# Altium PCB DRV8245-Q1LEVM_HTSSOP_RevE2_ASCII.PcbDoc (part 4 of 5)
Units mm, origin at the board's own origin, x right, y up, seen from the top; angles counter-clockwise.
Board outline 81.9 x 103.6 mm, 4 copper layers (Top Layer, Signal Layer 1, Signal Layer 2, Bottom Layer), stack 1.554 mm thick; 187 components, 116 nets, 590 pads, 1182 vias.
Unrouted connection lines stored in the file: 116.
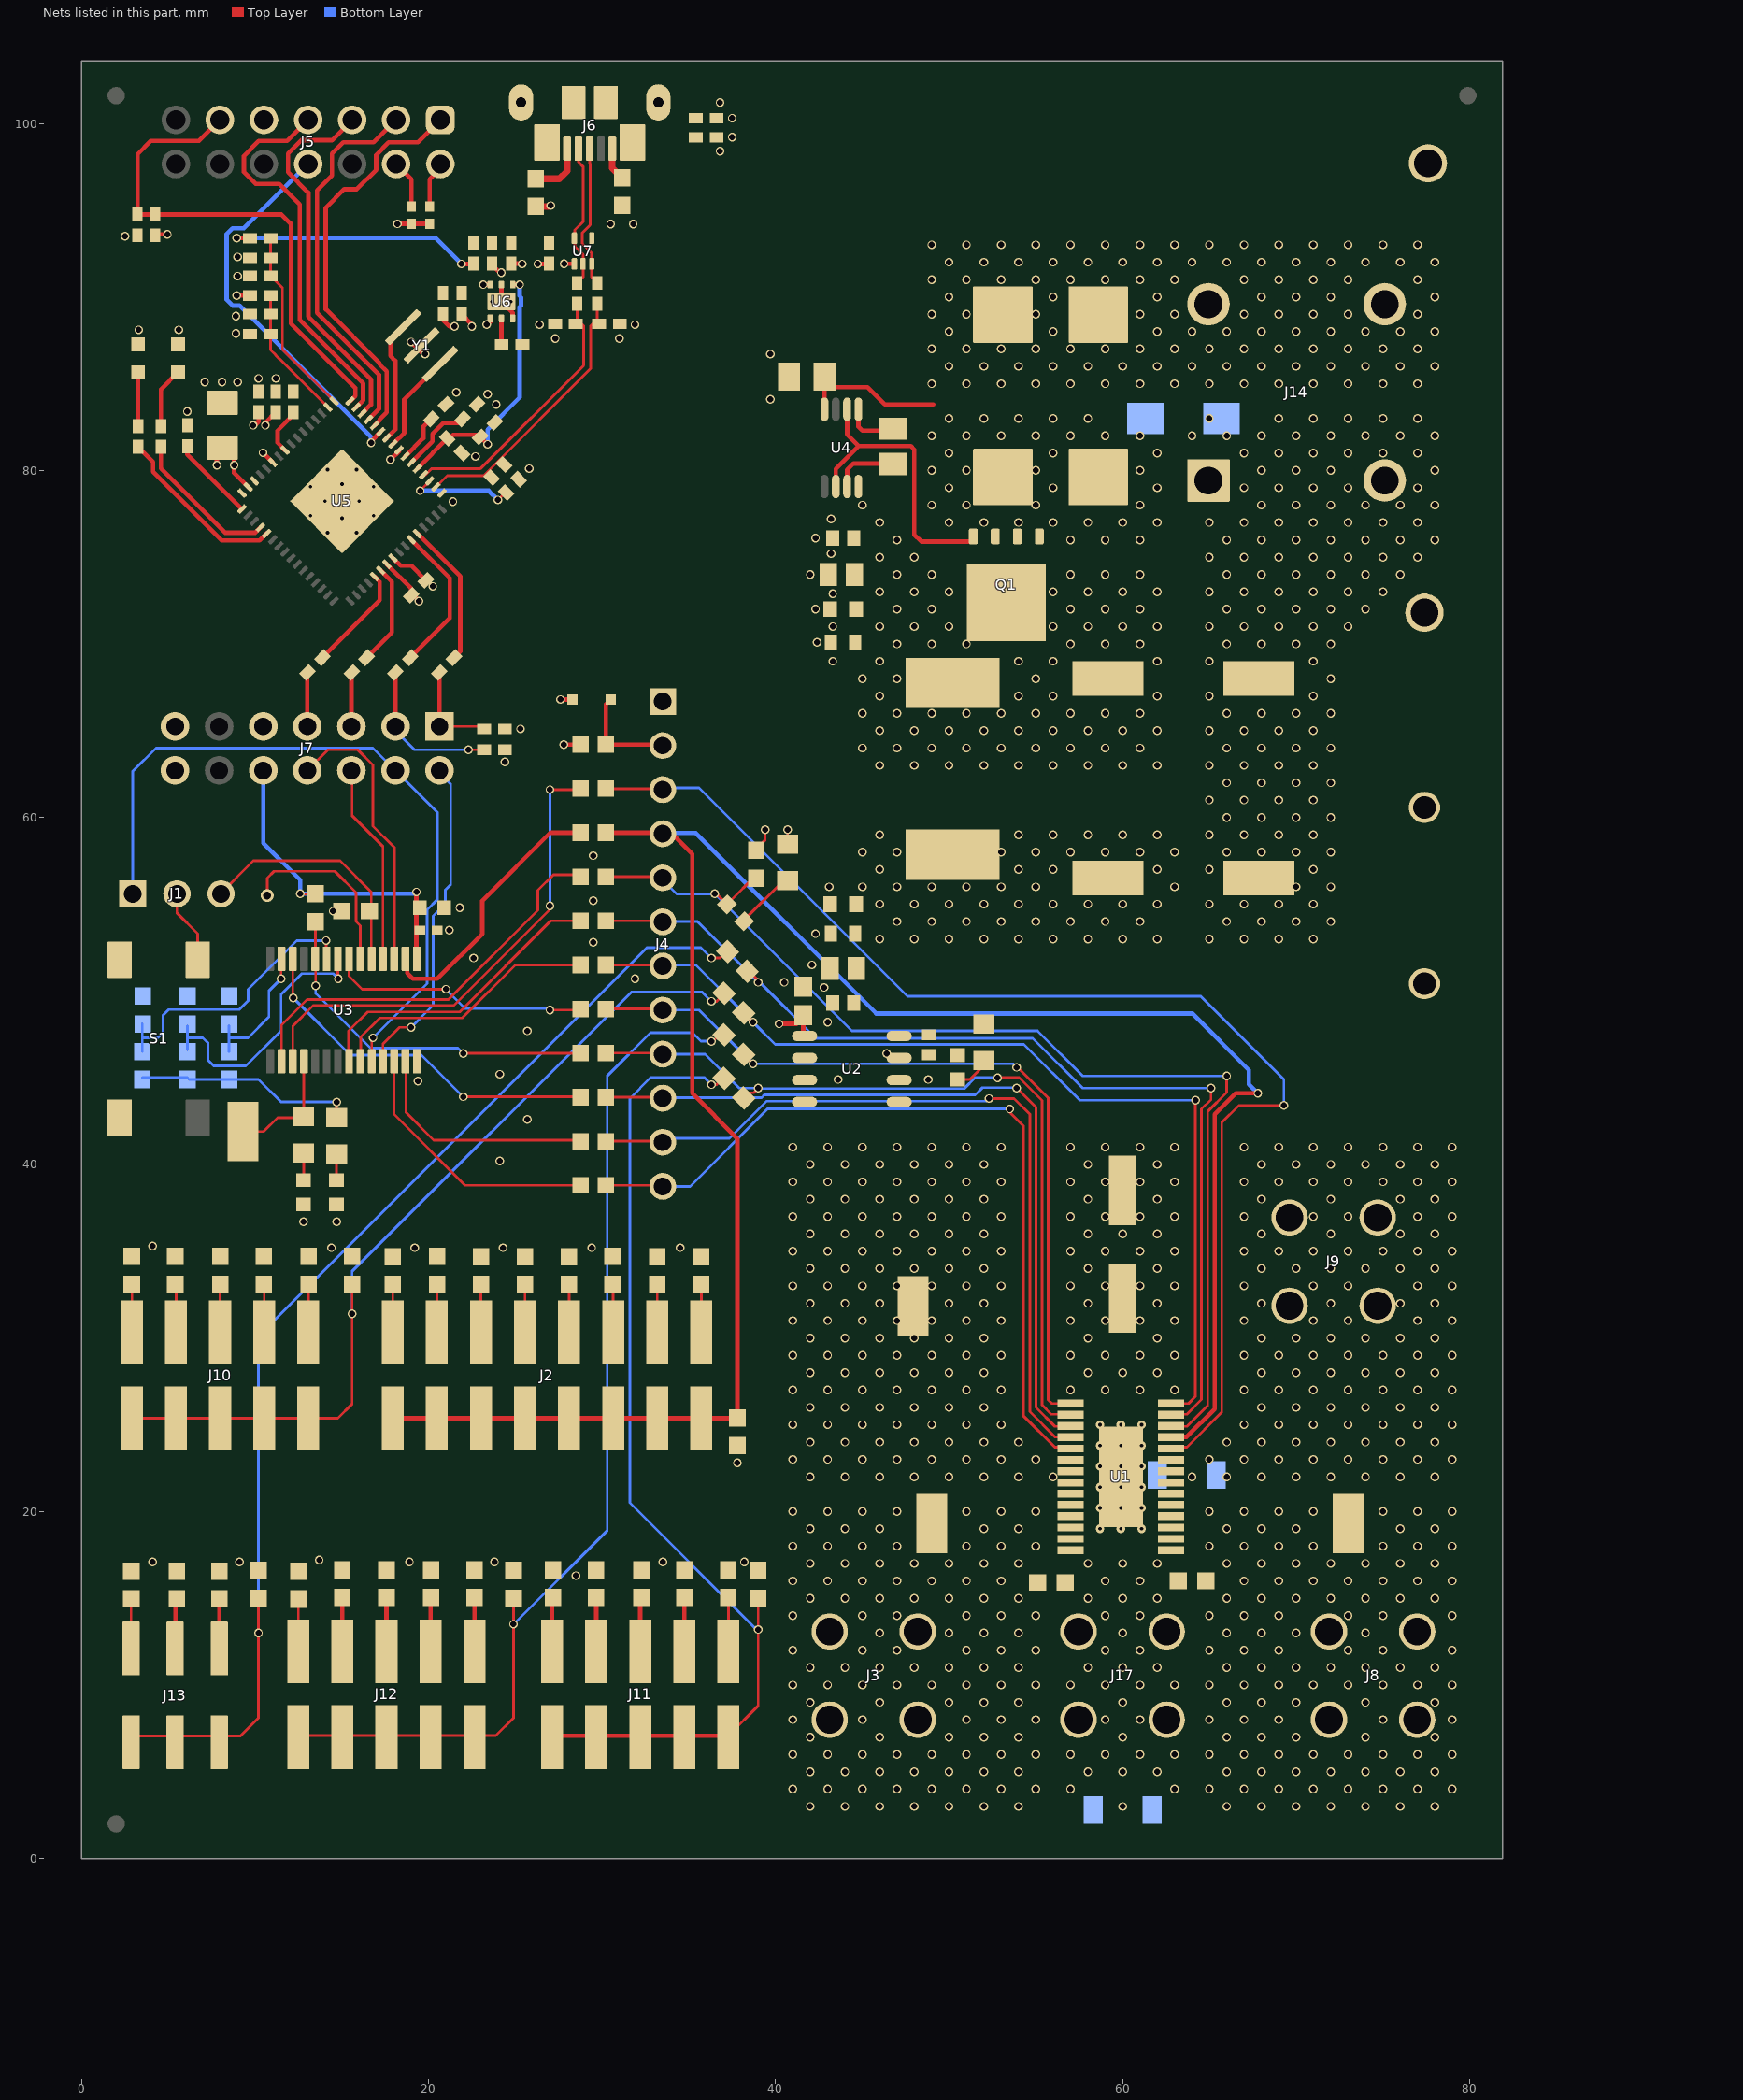
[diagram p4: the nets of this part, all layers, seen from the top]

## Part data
C1: library part CMP-0011164-2, "CAP, AL, 10 uF, 100 V, +/- 20%, AEC-Q200 Grade 3, SMD"
C2 C3: library part CMP-0008709-1, "CAP, CERM, 0.1 uF, 100 V, +/- 10%, X7R, 1206"
C4: library part CMP-13271-000011-1, "CAP CER 0.1UF 50V X7R 0603"
C5: library part CMP-13271-003053-1, "Cap Ceramic 22uF 6.3V X5R ±20% Pad SMD 0603 +85°C T/R"
C6 C13: library part CMP-2007-03579-1, "GRM21BR71H105KA12L"
C7 C12: library part CMP-1035-02591-1, "CAP 100nF 50V ±5% 0603 (1608 Metric) Thickness 1mm SMD"
C8 C11: library part CMP-1035-02321-3, "CAP CER 10000PF 50V X7R 0603"
C9 C10: library part CMP-0011178-2, "CAP, AL, 150 uF, 50 V, +/- 20%, 0.18 ohm, AEC-Q200 Grade 2, SMD"
C14 C15: library part CMP-03020-030804-1, "CAP CER 1000PF 50V X7R 0603"
C16: library part CMP-0007580-1, "CAP, CERM, 100 pF, 50 V, +/- 5%, C0G/NP0, 0805"
C17: library part CMP-0006268-2, "CAP, CERM, 4.7 uF, 10 V, +/- 10%, X5R, 0402"
C18: library part CMP-0064931-4, "CAP, CERM, 0.1 uF, 10 V,+/- 10%, X7R, 0603"
C19: library part CMP-0006269-2, "CAP, CERM, 4.7 uF, 10 V, +/- 20%, X5R, 0402"
C20 C22 C29 C35 C36 C37 C45: library part CMP-0006562-2, "CAP, CERM, 0.1 uF, 10 V, +/- 10%, X5R, 0402"
C21 C24: library part CMP-0006250-2, "CAP, CERM, 33 pF, 50 V, +/- 5%, C0G/NP0, 0402"
C23: library part CMP-0006673-2, "CAP, CERM, 1000 pF, 50 V, +/- 10%, X7R, 0402"
C25 C27 C44: library part CMP-0006570-2, "CAP, CERM, 0.22 uF, 10 V, +/- 10%, X5R, 0402"
C26: library part CMP-0006600-2, "CAP, CERM, 0.47 uF, 16 V, +/- 10%, X5R, 0402"
C28 C33: library part CMP-0064924-2, "CAP, CERM, 1 uF, 10 V,+/- 20%, X5R, 0402"
C30 C32: library part CMP-0006639-2, "CAP, CERM, 0.01 uF, 16 V, +/- 10%, X7R, 0402"
C31: library part CMP-0006594-2, "CAP, CERM, 2.2 uF, 16 V, +/- 10%, X5R, 0402"
C34: library part CMP-0084376-1, "CAP, Tantalum Polymer, 10 µF, 10 V,+/- 20%, 0.08 ohm, 3216-18 SMD"
C38 C39 C40 C41 C42 C43 C46: library part CMP-0007081-4, "CAP, CERM, 1000 pF, 100 V, +/- 10%, X7R, AEC-Q200 Grade 1, 0603"
C47 C48 C49 C50: library part CMP-0064916-2, "CAP, CERM, 10 pF, 50 V,+/- 1%, C0G/NP0, 0402"
C51: library part CMP-0007836-1, "CAP, CERM, 2.2 uF, 50 V, +/- 10%, X5R, 0805"
D1 D3 D7: library part CMP-1426-00009-1, "SMD mono-color Chip LED, WL-SMCW, Bright Green"
D2: library part CMP-1426-00010-1, "SMD mono-color Chip LED, WL-SMCW, Super Red"
D4: library part CMP-08607-000009-1, "TVS DIODE 36V 58.1V DO214AC"
D5: library part CMP-0002947-3, "LED, Red, SMD"
D6: "LED, Green, SMD"
D8: library part CMP-0028882-1, "Diode, Schottky, 40 V, 0.75 A, AEC-Q101, SOD-323"
F1 F2: library part CMP-0077200-3, "Fuse, 30 A, 250 VAC, 100 VDC, SMD"
FID1 FID2 FID3: library part CMP-0077181-1, "Fiducial mark.  There is nothing to buy or mount."
H1 H2 H3 H4: library part CMP-0003620-1, "Bumpon, Hemisphere, 0.44 X 0.20, Clear"
J1: library part CMP-77940-000002-1, "CONN HEADER VERT 3POS 2.54MM"
J2: library part CMP-0075595-1, "Header, 2.54mm, 8x2, Gold, SMT"
J3 J8 J9: library part CMP-0055418-2, "Banana Jack Insul Nylon Red, R/A, TH"
J4: library part CMP-0054586-1, "Header, 2.54 mm, 12x1, Gold, TH"
J5: library part CMP-0086014-1, "Header, 2.54mm, 7x2, Gold, TH"
J6: "Receptacle, USB 2.0, Micro B, 5 Position, R/A, SMT"
J7: library part CMP-0002339-2, "Header, 100mil, 7x2, Tin, TH"
J10 J11 J12: library part CMP-0055598-2, "Header, 2.54mm, 5x2, Gold, SMT"
J13: library part CMP-0079534-2, "Header, 2.54mm, 3x2, Gold, SMT"
J14: library part CMP-0086764-1
J15: library part CMP-0075110-1, "1mm Uninsulated Shorting Plug, 10.16mm spacing, TH"
J17: library part CMP-0055417-1, "Banana Jack Insul Nylon Black, R/A, TH"
L1: library part CMP-0226-00123-1, "SMD High Current Cube Inductor WE-HCC, L=1.00 µH"
L2 L3: library part CMP-0081962-1, "Ferrite Bead, 150 ohm @ 100 MHz, 0.7 A, 0603"
LBL1: library part CMP-0003625-1, "Thermal Transfer Printable Labels, 0.650\" W x 0.200\" H - 10,000 per roll"
Logo1: library part CMP-0074844-1
Logo2: library part CMP-0074838-1, "Texas Instrument Corporate Signature"
Logo3: library part CMP-0074847-1, "FCC_disclaimer"
Logo4: library part CMP-0074769-1
Logo5: library part CMP-0074836-1, "IEC 61010-1 Caution Warning"
LOGO6: library part CMP-0074837-1, "IEC 61010-1 Hot Surface Warning"
Q1: library part CMP-0000714-1, "MOSFET, N-CH, 40 V, 100 A, DQJ0008A (VSONP-8)"
R1 R68: library part CMP-0025886-3, "RES, 10 k, 5%, 0.1 W, 0603"
R2 R3 R20: "RES, 330, 5%, 0.1 W, AEC-Q200 Grade 0, 0603"
R4: library part CMP-0082533-1, "RES, 4.99 k, 1%, 0.1 W, 0603"
R5: library part CMP-0023129-5, "RES, 470, 1%, 0.1 W, 0603"
R6: library part CMP-0023235-5, "RES, 680, 1%, 0.1 W, 0603"
R7: library part CMP-0022895-5, "RES, 1.00 k, 1%, 0.1 W, 0603"
R8: library part CMP-0022883-5, "RES, 1.50 k, 1%, 0.1 W, 0603"
R9: library part CMP-0022986-5, "RES, 2.20 k, 1%, 0.1 W, 0603"
R10: library part CMP-0023081-5, "RES, 3.30 k, 1%, 0.1 W, 0603"
R11: library part CMP-0023153-5, "RES, 4.70 k, 1%, 0.1 W, 0603"
R12: library part CMP-0023253-5, "RES, 6.80 k, 1%, 0.1 W, 0603"
R13 R14 R15 R16 R17 R39 R40 R52: library part CMP-0086358-1, "RES, 0, 0%, 0.25 W, AEC-Q200 Grade 0, 0603"
R18: library part CMP-0025925-5, "RES, 47 k, 5%, 0.1 W, 0603"
R19 R22 R23 R24 R25 R26 R27 R28 R29 R30 R31: library part CMP-2000-03817-1
R21 R67 R69 R70 R71 R72: library part CMP-0025886-5, "RES, 10 k, 5%, 0.1 W, 0603"
R32: library part CMP-0026190-2, "RES, 240 k, 1%, 0.063 W, AEC-Q200 Grade 0, 0402"
R33: library part CMP-0026934-3, "RES, 470, 5%, 0.063 W, AEC-Q200 Grade 0, 0402"
R34: library part CMP-0026914-3, "RES, 390, 5%, 0.063 W, AEC-Q200 Grade 0, 0402"
R35: library part CMP-0026021-3, "RES, 150 k, 1%, 0.063 W, AEC-Q200 Grade 0, 0402"
R36 R38: library part CMP-0026728-1, "RES, 220 k, 1%, 0.0625 W, 0402"
R37: library part CMP-0026935-3, "RES, 47 k, 5%, 0.063 W, AEC-Q200 Grade 0, 0402"
R41 R42: library part CMP-0026992-3, "RES, 0, 5%, 0.1 W, AEC-Q200 Grade 0, 0402"
R43 R44: library part CMP-0026888-3, "RES, 27, 5%, 0.063 W, AEC-Q200 Grade 0, 0402"
R45: library part CMP-0026085-3, "RES, 1.40 k, 1%, 0.063 W, AEC-Q200 Grade 0, 0402"
R46: library part CMP-0026859-2, "RES, 1.0 M, 5%, 0.063 W, AEC-Q200 Grade 0, 0402"
R47 R48 R49 R50: library part CMP-0025963-2, "RES, 10.0, 1%, 0.063 W, 0402"
R51: library part CMP-0026907-3, "RES, 33 k, 5%, 0.063 W, AEC-Q200 Grade 0, 0402"
R53 R54 R55 R56: library part CMP-0025862-3, "RES, 8.2 k, 5%, 0.1 W, 0603"
R57 R58 R59: library part CMP-0025757-4, "RES, 22 k, 5%, 0.1 W, AEC-Q200 Grade 0, 0603"
R60: library part CMP-0025860-2, "RES, 82 k, 5%, 0.1 W, 0603"
R61 R62 R63: library part CMP-0022438-1, "RES, 47.0 k, 1%, 0.1 W, AEC-Q200 Grade 0, 0603"
R64 R65 R66: library part CMP-0086261-1, "RES, 100 k, 0.5%, 0.1 W, AEC-Q200 Grade 0, 0603"
S1: library part CMP-0002134-3, "Switch, Tactile, SPST-NO, 0.05A, 12V, SMT"
TP1 TP2 TP5 TP6: library part CMP-0055152-1, "Test Point, Miniature, SMT"
TP3: library part CMP-0003719-1, "Testpoint"
TP8: library part CMP-0055147-1, "Test Point, Multipurpose, Red, TH"
TP9: library part CMP-0055148-1, "Test Point, Multipurpose, Black, TH"
U1: library part DRV8245S-Q1-HTSSOP-28, "DRV8245S-Q1 HTSSOP 28-pin leaded package"
U2: library part CMP-0070570-1, "Ultra-Low Quiescent Current Voltage Regulator, 8-pin Narrow SOIC, Pb-Free"
U3: library part CMP-0365-00685-2, "16 MHz Mixed Signal Microcontroller with 16 KB Flash, 512 B SRAM and 24 GPIOs, -40 to 85 degC, 28-pin SOP (PW), Green (RoHS & no Sb/Br)"
U4: library part CMP-0076397-2, "Zero Iq Reverse Polarity Protection Smart Diode Controller, DGK0008A (VSSOP-8)"
U5: "16-Bit Ultra-Low-Power Microcontroller, 128KB Flash, 8KB RAM, USB, 12Bit ADC, 2 USCIs, 32Bit HW MPY, RGC0064B (VQFN-64)"
U6: library part CMP-0036330-5, "Single Output High PSRR LDO, 500 mA, Fixed 3.3 V Output, 2.7 to 6.5 V Input, with Low IQ, 6-pin SON (DRV), -40 to 125 degC, Green (RoHS & no Sb/Br)"
U7: library part CMP-0043096-2, "Low-Capacitance + / - 15 kV ESD-Protection Array for High-Speed Data Interfaces, 2 Channels, -40 to +85 degC, 5-pin SOT (DRL), Green (RoHS & no Sb/Br)"
Y1: library part CMP-0085483-1, "Oscillator, 4 MHz, 700 ppm, 39 pF, SMD"
ZZ1: library part CMP-0003616-3
ZZ2: library part CMP-0077236-1
ZZ3: library part CMP-0077237-1
ZZ4: library part CMP-0077238-1

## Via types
v1: diameter 0.5, hole 0.35, Top Layer to Bottom Layer, tented both sides, 1150 vias
v2: diameter 0.5, hole 0.2, Top Layer to Bottom Layer, 32 vias

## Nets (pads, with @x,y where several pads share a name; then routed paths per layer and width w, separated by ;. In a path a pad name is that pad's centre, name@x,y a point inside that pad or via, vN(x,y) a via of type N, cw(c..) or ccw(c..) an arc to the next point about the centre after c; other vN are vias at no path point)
3V3: C5.1 D2.2 D8.1 J4.2 R1.2 R19.2 U2.1 | length 10.9
  Top Layer w0.152: R1.2@38.8,58.1 39.4,58.7 v1(39.4,59.3) ; D2.2@40.7,58.5 v1(40.7,59.3)
  Top Layer w0.254: D8.1@30.5,66.8 30.225,66.525 R19.2@30.225,64.2 J4.2@33.4,64.2 ; v1(40.2,48.1) 41.2,48.1 C5.1@41.6,48.5 ; U2.1@41.6,47.4 C5.1@41.6,48.5 ; C5.1@41.6,48.6 C5.1@41.6,48.5
3V3_MCU: C17.1 C18.1 D7.2 D8.2 J7.10 R18.2 R19.1 R21.1 R67.1 R68.1 R69.1 U3.1 | length 34.6
  Top Layer w0.152: v1(12.6,55.6) R68.1@13.5,55.6 ; v1(14.5,54.6) R18.2@15,54.6 R18.2@15.3,54.6 ; D7.2@14.7,42.7 v1(14.7,43.6)
  Top Layer w0.254: U3.1@19.3,51.7 v1(19.3,55.7) ; v1(27.6,66.8) D8.2@28.3,66.8 ; v1(27.8,64.2) 28.6,64.2 R19.1@28.7,64.1
  Bottom Layer w0.152: R21.1@3.5,45 R67.1@6.1,45 ; R67.1@6.2,44.9 R69.1@8.5,44.9 10.2,44.9 11.5,43.6 v1(14.7,43.6)
  Bottom Layer w0.254: J7.10@10.475,62.708 10.475,58.525 12.6,56.4 v1(12.6,55.6) 19.1,55.6 v1(19.3,55.7)
DRVOFF: J4.12 R22.2 U1.5 | length 46.3
  Top Layer w0.152: R22.2@30.225,38.8 J4.12@33.2,38.8 ; v1(53.5,43.2) 53.5,43 54.3,42.2 54.3,25.5 56.1,23.7 56.925,23.7 U1.5@57,23.625
  Bottom Layer w0.152: J4.12@33.5,38.74 35.081,38.74 39.541,43.2 v1(53.5,43.2)
DRVOFF_MCU: R22.1 U3.26 | length 15.7
  Top Layer w0.152: U3.26@18.025,45.95 18,45.925 18,42.9 22.1,38.8 R22.1@28.9,38.8
EN/IN1: J4.11 R23.2 U1.4 | length 45.6
  Top Layer w0.152: R23.2@30.225,41.34 J4.11@33.26,41.34 ; v1(52.3,43.8) 53.744,43.8 54.652,42.892 54.652,25.748 56.1,24.3 56.975,24.3 U1.4@57,24.275
  Bottom Layer w0.152: J4.11@33.5,41.5 37.343,41.5 39.495,43.652 52.152,43.652 v1(52.3,43.8)
EN/IN1_MCU: R23.1 U3.27 | length 13.9
  Top Layer w0.152: U3.27@18.675,45.95 18.7,45.925 18.7,43 20.3,41.4 28.8,41.4 R23.1@28.9,41.3
EZFET_AVBUS: C21.1 R32.1 R35.2 U5.1 | length 10.8
  Top Layer w0.152: R32.1@10.923,93.307 10.902,93.286 C21.1@10.902,91.208 10.902,91.203 11.581,90.524 11.581,86.971 U5.1@14.556,83.996
EZFET_AVCC2ADC: C24.1 R36.1 R38.2 U5.2 | length 12
  Top Layer w0.152: R36.1@10.905,90.081 10.905,86.94 ; U5.2@14.203,83.642 11.424,86.421 11.396,86.421 11.19,86.627 11.19,86.655 10.905,86.94 ; 10.905,86.94 R38.2@10.905,89.02 10.905,86.94
EZFET_D_N: C49.1 R43.2 U5.52 | length 16.6
  Top Layer w0.16: U5.52@19.718,79.753 19.831,79.753 20.185,80.107 23,80.107 28.937,86.044 28.937,88.33 ; R43.2@28.559,89.608 C49.1@28.559,88.708 ; C49.1@28.559,88.708 28.937,88.33 ; C49.1@28.559,88.708 28.937,88.33 ; C49.1@28.559,88.708 28.937,88.33
EZFET_D_P: C50.1 R44.2 R45.1 R46.2 U5.50 | length 16.4
  Top Layer w0.16: U5.50@20.425,79.046 21.072,79.693 23.171,79.693 23.361,79.883 ; R45.1@23.627,79.579 23.627,79.617 23.361,79.883 ; R46.2@24.101,80.591 R46.2@24.35,80.342 ; R44.2@29.728,89.608 29.728,88.708 29.351,88.33 29.351,85.872 23.361,79.883
EZFET_LED0: R33.2 U5.20 | length 8.6
  Top Layer w0.254: R33.2@4.578,81.356 4.578,80.106 8.268,76.416 10.017,76.416 U5.20@10.314,76.713
EZFET_LED1: R34.2 U5.21 | length 10.1
  Top Layer w0.254: R34.2@3.258,81.356 4.124,80.49 4.124,79.918 8.08,75.962 10.262,75.962 10.659,76.359 U5.21@10.667,76.359
EZFET_PUR: R45.2 U5.51 | length 6.2
  Top Layer w0.152: v1(19.516,78.83) 20.072,79.386 U5.51@20.072,79.4 ; v1(24,78.3) R45.2@24.5,78.8
  Bottom Layer w0.254: v1(19.516,78.83) 23.47,78.83 v1(24,78.3)
EZFET_RST: C23.1 J5.11 R37.1 U5.64 | length 30
  Top Layer w0.254: J5.11@7.976,100.2 6.771,98.995 3.998,98.995 3.228,98.224 C23.1@3.228,94.749 R37.1@4.228,94.749 11.535,94.749 12.076,94.208 12.076,88.458 15.778,84.756 15.778,84.298 U5.64@15.476,83.996
EZFET_TCK: J5.7 U5.63 | length 22.8
  Top Layer w0.254: J5.7@13.056,100.2 11.851,98.995 10.222,98.995 9.364,98.137 9.364,97.182 10.039,96.508 11.395,96.508 12.576,95.327 12.576,88.665 16.232,85.009 16.232,84.045 U5.63@15.829,83.642
EZFET_TDI: J5.3 U5.61 | length 21.9
  Top Layer w0.254: U5.61@16.536,82.935 17.14,83.538 17.14,85.515 13.576,89.079 13.576,96.14 14.444,97.008 14.444,98.259 15.089,98.904 16.841,98.904 J5.3@18.136,100.2
EZFET_TDO: J5.1 U5.60 | length 23.5
  Top Layer w0.254: U5.60@16.89,82.581 17.192,82.883 17.192,82.948 17.594,83.35 17.594,85.703 17.192,86.105 17.192,86.17 14.076,89.286 14.076,95.134 15.15,96.208 15.866,96.208 16.984,97.326 16.984,98.187 17.701,98.904 19.381,98.904 J5.1@20.676,100.2
EZFET_TEST: J5.8 U5.59 | length 22.9
  Top Layer w0.254: v1(16.689,81.595) 16.689,81.673 U5.59@17.243,82.228
  Bottom Layer w0.254: J5.8@13.056,97.66 9.356,93.96 8.706,93.96 8.368,93.622 8.368,89.842 8.706,89.504 9.112,89.504 16.689,81.927 v1(16.689,81.595)
EZFET_TMS: J5.5 U5.62 | length 21.7
  Top Layer w0.254: J5.5@15.596,100.2 14.428,99.031 12.667,99.031 11.904,98.269 11.904,97.182 13.076,96.01 13.076,88.872 16.686,85.262 16.686,83.791 U5.62@16.183,83.289
EZFET_UARTRXD: R49.1 U5.38 | length 5.9
  Top Layer w0.254: R49.1@16.427,69.208 17.88,70.661 17.88,73.601 U5.38@17.243,74.238
EZFET_UARTTXD: R50.1 U5.37 | length 6.2
  Top Layer w0.254: R50.1@13.88,69.206 17.192,72.518 17.192,73.582 U5.37@16.89,73.884
EZFET_USB_Shield: C44.1 J6.6 J6.7 J6.8 J6.9 J6.10 J6.11 R51.2
EZFET_V18: C25.1 U5.55 | length 2.8
  Top Layer w0.254: U5.55@18.658,80.814 19.699,81.853 19.699,82.506 C25.1@20.159,82.966
EZFET_VBUS: C19.1 C20.1 C28.1 C29.1 C30.1 C45.1 L2.2 R32.2 U5.53 U6.4 U6.6 U7.1 | length 34.3
  Top Layer w0.152: U6.6@23.551,90.709 U6.6@23.551,90.709 ; v1@24.1,91.4 v1(24.2,91.4) ; U6.4@24.851,90.709 U6.4@24.851,90.709 ; v1@25.375,91.925 v1(25.4,91.9) ; U7.1@28.381,91.925 U7.1@28.403,91.903
  Top Layer w0.254: v1(8.945,93.383) R32.2@9.714,93.383 ; U5.53@19.365,80.107 C20.1@21.077,81.853 21.22,81.853 21.417,82.05 22.846,82.05 23.396,81.5 v1(23.4,81.5) ; v1(21.9,91.9) C28.1@22.6,91.9 ; v1(23.151,90.708) U6.6@23.551,90.709 ; C29.1@23.7,91.8 v1@24.1,91.4 ; C30.1@24.774,91.925 v1@25.375,91.925 ; U6.4@24.851,90.709 v1(25.251,90.708) ; v1(26.3,91.9) C45.1@26.9,91.9 ; v1(27.815,91.903) 28.358,91.903 U7.1@28.381,91.925
  Top Layer w0.381: L2.2@26.174,95.21 26.98,95.21 v1(27.036,95.266)
  Bottom Layer w0.254: v1(8.945,93.383) 20.417,93.383 v1(21.9,91.9) ; v1(23.4,81.5) 23.4,82.35 25.251,84.201 25.251,89.418 25.328,89.495 25.328,89.973 25.251,90.05 v1(25.251,90.708)
EZFET_VCC: C31.1 C33.1 C34.1 C35.1 C36.1 C37.1 J7.9 R36.2 R37.2 R41.1 R42.1 U5.11 U5.15 U5.40 U6.1 | length 14.9
  Top Layer w0.152: C34.1@8.7,81 C34.1@8.8,80.9 ; C37.1@19.854,73.657 19.903,73.657 v1(20.247,73.314)
  Top Layer w0.254: R37.2@4.228,93.549 4.278,93.599 v1(4.95,93.599) ; v1(7.8,80.3) C34.1@7.8,81.2 ; C34.1@8.8,80.9 v1(8.8,80.3) 8.8,79.853 U5.15@9.607,79.046 ; v1(8.945,90.081) R36.2@9.705,90.081 ; v1(9.9,82.6) 10,82.6 10.205,82.805 C36.1@10.205,83.35 ; v1(10.46,81.021) U5.11@11.021,80.46 ; v1(10.6,82.6) 10.6,82.76 C35.1@11.19,83.35 ; U5.40@17.951,74.945 18.39,74.506 19.005,74.506 C37.1@19.854,73.657 ; v1(18.213,94.208) 18.889,94.208 18.95,94.146 R41.1@19.011,94.208 R42.1@20.062,94.208 ; C33.1@20.831,89.025 20.831,88.669 21.2,88.3 v1(21.5,88.3) ; C31.1@21.9,89.02 22.5,88.42 v1(22.5,88.3) ; v1(23.351,88.406) 23.551,88.549 U6.1@23.551,88.759
EZFET_Vcore: C26.1 U5.17 | length 4.9
  Top Layer w0.254: C26.1@6.228,81.356 6.1,81.228 6.1,80.926 U5.17@9.253,77.773
EZFET_VREF: C22.1 U5.9 | length 2.7
  Top Layer w0.254: U5.9@11.728,81.167 11.3,81.595 11.3,82.298 12.2,83.198 C22.1@12.2,83.35
EZFET_VUSB: C27.1 U5.54 | length 6.6
  Top Layer w0.254: U5.54@19.011,80.46 20.227,81.674 20.227,82.105 20.843,82.72 ; C27.1@21.958,82.966 C27.1@21.958,82.72 ; 20.843,82.72 C27.1@21.958,82.72 ; 20.843,82.72 C27.1@21.958,82.72 ; 20.843,82.72 C27.1@21.958,82.72
EZFET_XT2IN: U5.57 Y1.1 | length 5.1
  Top Layer w0.254: U5.57@17.951,81.521 18.6,82.17 18.6,84.1 Y1.1@20.2,85.7
EZFET_XT2OUT: U5.58 Y1.3 | length 5.9
  Top Layer w0.254: U5.58@17.597,81.874 18.083,82.361 18.083,86.317 17.8,86.6 Y1.3@17.8,87.5
GND: C1.2 C2.2 C4.2 C5.2 C6.1 C7.1 C8.1 C9.2 C10.2 C11.2 C12.1 C13.1 C14.2 C15.2 C16.2 C17.2 C18.2 C19.2 C20.2 C21.2 C22.2 C23.2 C24.2 C25.2 C26.2 C27.2 C28.2 C29.2 C30.2 C31.2 C32.2 C33.2 C34.2 C35.2 C36.2 C37.2 C38.1 C39.1 C40.1 C41.1 C42.1 C43.1 C44.2 C45.2 C46.1 C47.1 C48.1 C49.2 C50.2 D4.1 D5.1 D6.1 J4.1 J5.9 J7.13 J7.14 J14.1 J15.1 J15.2 J17.1 L3.2 R2.1 R4.1 R5.1 R6.1 R7.1 R8.1 R9.1 R10.1 R11.1 R12.1 R13.2 R15.2 R17.2 R20.1 R35.1 R38.1 R40.2 R46.1 R51.1 R53.1 R54.1 R55.1 R56.1 R57.1 R58.1 R59.1 R60.2 R61.1 R62.1 R63.1 R64.1 R65.1 R66.1 R70.2 R71.2 R72.2 S1.3 S1.4 TP9.1 U1.12 U1.13 U1.14 U1.15 U1.16 U1.17 U1.29 U2.2 U2.3 U2.4 U2.5 U2.6 U2.7 U3.28 U5.14 U5.16 U5.39 U5.49 U5.56 U5.65 U6.3 U6.5 U6.7@24.201,89.734 U7.4 Y1.2 | length 7
  Top Layer w0.152: C37.2@19.005,72.809 C37.2@19.111,72.809 ; v1@19.7,86.7 v1(19.8,86.7)
  Top Layer w0.254: U5.39@17.597,74.591 19.005,73.183 C37.2@19.005,72.809 ; v1(17.803,80.619) 18.304,81.121 U5.56@18.304,81.167 ; v1(19,87.4) v1@19.7,86.7 ; C37.2@19.111,72.809 v1(19.45,72.47) ; U6.5@24.201,90.709 U6.7@24.201,89.734 24.851,89.084 U6.3@24.851,88.759
  other v1: 60,3 57,4 63,4 58,5 60,5 62,5 57,6 59,6 61,6 63,6 60,7 59,8 61,8 60,9 57,10 59,10 61,10 63,10 58,11 60,11 62,11 59,12 61,12 60,13 59,14 61,14 58,15 60,15 62,15 59,16 61,16 28.5,16.3 58,17 60,17 62,17 4.1,17.1 9.1,17.1 18.9,17.1 23.8,17.1 33.5,17.1 38.2,17.1 13.7,17.2 37.8,22.8 57,27 59,27 61,27 63,27 58,28 60,28 62,28 57,29 59,29 61,29 63,29 58,30 62,30 57,31 59,31 61,31 63,31 58,32 62,32 57,33 59,33 61,33 63,33 58,34 62,34 57,35 59,35 61,35 63,35 14.4,35.2 19.2,35.2 24.3,35.2 29.4,35.2 34.5,35.2 4.1,35.3 12.8,36.7 14.7,36.7 24.1,40.2 25.7,42.6 19.4,44.8 43.6,44.9 48.8,44.9 24.1,45.2 46.4,46.4 25.7,47.7 43,48.2 42.8,50.2 40.5,50.5 31.9,50.7 42.1,51.5 22.6,51.9 29.5,52.8 65,53 67,53 69,53 71,53 42.3,53.3 21.2,53.5 66,54 68,54 70,54 72,54 21.8,54.8 65,55 67,55 69,55 71,55 29.5,55.2 43.1,56 70,56 72,56 65,57 71,57 29.5,57.8 66,58 68,58 70,58 72,58 65,59 67,59 69,59 71,59 66,60 68,60 70,60 72,60 65,61 67,61 69,61 71,61 66,62 68,62 70,62 72,62 65,63 67,63 69,63 71,63 24.4,63.2 66,64 68,64 70,64 72,64 65,65 67,65 69,65 71,65 25.3,65.1 66,66 68,66 70,66 72,66 65,67 71,67 72,68 43.3,69 65,69 71,69 66,70 68,70 70,70 72,70 42.4,70.1 43.3,71 65,71 67,71 69,71 71,71 73,71 42.3,72 66,72 68,72 70,72 72,72 74,72 43.3,72.9 65,73 67,73 69,73 71,73 73,73 75,73 42,74 66,74 68,74 70,74 72,74 74,74 76,74 65,75 67,75 69,75 71,75 73,75 75,75 77,75 43.2,75.2 66,76 68,76 70,76 72,76 74,76 76,76 78,76 42.3,76.1 65,77 67,77 69,77 71,77 73,77 75,77 77,77 43.2,77.2 68,78 70,78 72,78 74,78 76,78 78,78 21.4,78.2 67,79 69,79 71,79 73,79 77,79 68,80 70,80 72,80 78,80 25.8,80.1 22.7,80.8 67,81 69,81 71,81 73,81 75,81 77,81 64,82 66,82 68,82 70,82 72,82 74,82 76,82 78,82 65,83 69,83 71,83 73,83 75,83 77,83 6.1,83.4 23.9,83.8 39.7,84.1 23.4,84.4 21.6,84.5 7.1,85.1 8.1,85.1 9,85.1 10.2,85.3 11.2,85.3 39.7,86.7 27.3,87.6 31,87.6 8.9,87.9 3.3,88.1 5.6,88.1 26.4,88.4 31.9,88.4 8.9,88.9 9,91.2 9,92.3 2.5,93.5 30.5,94.2 31.8,94.2 36.8,98.4 37.5,99.2 37.5,100.3 36.8,101.2
  other v2: 58.7,19 59.9,19 61.1,19 58.7,20.2 59.9,20.2 61.1,20.2 58.7,21.4 59.9,21.4 61.1,21.4 58.7,22.6 59.9,22.6 61.1,22.6 58.7,23.8 59.9,23.8 61.1,23.8 58.7,25 59.9,25 61.1,25 14.182,76.416 15.85,76.416 15.016,77.25 13.199,77.398 16.833,77.398 14.033,78.233 15.999,78.233 13.199,79.067 16.833,79.067 15.016,79.216 14.182,80.05 15.85,80.05 23.651,89.734 24.751,89.734
ID1: R21.2 R70.1 U3.9 | length 16.7
  Top Layer w0.152: v1(14.1,52.9) 14.1,52 U3.9@14.2,51.9
  Bottom Layer w0.152: R21.2@3.5,46.5 3.5,47.3 ; R70.1@3.5,48.1 3.5,47.3 ; 10.6,51.1 12.4,52.9 v1(14.1,52.9) ; 10.7,51.2 9.6,50.1 9.6,49.434 9.089,48.924 5.024,48.924 4.7,48.6 4.7,47.6 4.4,47.3 3.5,47.3
ID2: R67.2 R71.1 U3.8 | length 16.2
  Top Layer w0.152: U3.8@14.775,51.85 14.775,50.625 v1@14.8,50.6
  Bottom Layer w0.152: R67.2@6.1,46.6 6.1,47.3 ; R71.1@6.1,48 6.1,47.3 ; v1(14.8,50.7) 14.5,51 12.7,51 11.5,49.8 11.5,47.7 9.476,45.676 7.624,45.676 7.3,46 7.3,47 7,47.3 6.1,47.3
ID3: R69.2 R72.1 U3.13 | length 8
  Top Layer w0.152: v1(11.5,50.7) U3.13@11.5,51.9
  Bottom Layer w0.152: R69.2@8.5,46.5 8.5,47.3 ; R72.1@8.5,48 8.5,47.3 ; v1(11.5,50.7) 10.8,50 10.8,48.5 9.6,47.3 8.5,47.3
IPROPI: C42.2 J2.2 J2.4 J2.6 J2.8 J2.10 J2.12 J2.14 J2.16 J4.4 R30.2 U1.25 | length 122.9
  Top Layer w0.254: J2.16@17.942,25.376 J2.14@20.482,25.376 J2.12@23.022,25.376 J2.10@25.562,25.376 J2.8@28.102,25.376 J2.6@30.642,25.376 J2.4@33.182,25.376 J2.2@35.624,25.376 ; R30.2@30.225,59.12 J4.4@33.28,59.12 ; J4.4@33.5,59.1 34,59.1 35.2,57.9 35.2,44.1 37.8,41.5 37.8,39.9 ; J2.2@35.722,25.376 C42.2@37.824,25.376 ; C42.2@37.8,25.4 37.8,40 ; U1.25@62.8,24.275 62.825,24.3 63.7,24.3 65.308,25.908 65.308,42.887 66.521,44.1 v1(67.8,44.1)
  Bottom Layer w0.254: J4.4@33.5,59 33.6,59.1 35.4,59.1 45.8,48.7 64.016,48.7 67.277,45.439 67.277,44.623 v1(67.8,44.1)
IPROPI_MCU: R30.1 U3.2 | length 15.7
  Top Layer w0.254: U3.2@18.6,51.8 18.6,51.288 18.773,51.288 18.773,51.027 19.1,50.7 20.5,50.7 23.1,53.3 23.1,55.2 27.02,59.12 R30.1@28.775,59.12
MCU_UARTRXD: J7.8 U3.3 | length 16.3
  Top Layer w0.152: J7.8@13,62.7 14.2,63.9 15.92,63.9 16.8,63.02 16.8,59.5 18.025,58.275 U3.3@18.025,51.85
MCU_UARTTXD: J7.6 U3.4 | length 11.6
  Top Layer w0.152: J7.6@15.6,62.7 15.6,60.1 17.376,58.324 17.376,51.851 U3.4@17.375,51.85
NetC32_1: C32.1 U6.2 | length 1.5
  Top Layer w0.254: C32.1@24.051,87.405 C32.1@24.06,87.396 ; U6.2@24.201,88.759 24.201,87.269 C32.1@24.214,87.256
NetC40_2: C40.2 J13.2 J13.4 J13.6 R52.2 | length 68.5
  Top Layer w0.152: J13.6@2.87,7.056 7.944,7.056 J13.2@8,7 ; J13.2@7.95,7.056 9.156,7.056 10.2,8.1 v1(10.2,13) C40.2@10.2,14.9 ; C40.2@10.4,14.9 C40.2@10.4,15 ; v1(36.3,51.9) 36.8,51.9 R52.2@37.2,52.3
  Bottom Layer w0.152: v1(10.2,13) 10.2,30.1 32.591,52.491 35.709,52.491 v1(36.3,51.9)
NetC41_2: C41.2 J12.2 J12.4 J12.6 J12.8 J12.10 R39.2 | length 61.7
  Top Layer w0.152: J12.10@12.497,7.081 22.619,7.081 J12.2@22.7,7 ; J12.2@22.657,7.081 23.881,7.081 24.9,8.1 v1(24.9,13.5) C41.2@24.9,14.9 ; v1(36.3,47.1) 36.4,47.1 36.8,47.5 R39.2@37,47.3
  Bottom Layer w0.152: v1(24.9,13.5) 30.3,18.9 30.3,45.1 32.8,47.6 35.2,47.6 35.7,47.1 v1(36.3,47.1)
NetC43_2: C43.2 J10.2 J10.4 J10.6 J10.8 J10.10 R14.2 | length 50.8
  Top Layer w0.152: J10.10@2.956,25.376 J10.8@5.45,25.376 J10.6@7.99,25.376 J10.4@10.53,25.376 J10.2@13.07,25.376 13.076,25.376 J10.2@13.1,25.4 ; J10.2@13.116,25.376 14.776,25.376 15.6,26.2 v1(15.6,31.4) C43.2@15.6,33.1 ; v1(36.3,49.4) 36.6,49.4 R14.2@37,49.8
  Bottom Layer w0.152: v1(15.6,31.4) 15.6,33.844 31.707,49.951 35.749,49.951 v1(36.3,49.4)
NetC46_2: C46.2 J11.2 J11.4 J11.6 J11.8 J11.10 R16.2 | length 58.8
  Top Layer w0.152: v1(36.3,44.6) 36.6,44.6 R16.2@37,45 ; J11.2@37.284,7.081 39,8.797 v1(39,13.2) C46.2@39,15
  Top Layer w0.254: J11.10@27.124,7.081 J11.2@37.284,7.081
  Bottom Layer w0.152: v1(36.3,44.6) 35.9,45 32.8,45 31.6,43.8 31.6,20.5 v1@39,13.1
NetC47_2: C47.2 J7.1 R47.2 | length 5.7
  Top Layer w0.152: J7.1@20.635,65.248 23.052,65.248 C47.2@23.2,65.1
  Top Layer w0.254: R47.2@20.619,68.358 20.635,68.341 J7.1@20.635,65.248
NetC48_2: C48.2 J7.3 R48.2 | length 8.9
  Top Layer w0.152: v1(22.3,63.9) C48.2@23.2,63.9
  Top Layer w0.254: J7.3@18.095,65.248 R48.2@18.095,68.358
  Bottom Layer w0.152: J7.3@18.095,65.248 18.095,65.005 19.2,63.9 v1(22.3,63.9)
NetC51_1: C51.1 U4.7 | length 3.8
  Top Layer w0.254: U4.7@44.125,79.075 44.125,80.025 44.5,80.4 C51.1@46.8,80.4
NetC51_2: C51.2 U4.1 | length 3.1
  Top Layer w0.254: U4.1@44.775,83.525 44.775,82.525 45,82.3 C51.2@46.8,82.3
NetD1_1: D1.1 R2.2 | length 1.5
  Top Layer w0.152: R2.2@12.8,39.1 12.8,40.5 D1.1@12.9,40.6
NetD2_1: D2.1 R3.2 | length 3.5
  Top Layer w0.152: R3.2@38.195,54.005 38.195,54.095 40.4,56.3 D2.1@40.7,56.3
NetD3_1: D3.1 R4.2 | length 2
  Top Layer w0.152: R4.2@50.5,44.9 51.2,44.9 D3.1@52.1,45.8
NetD5_2: D5.2 R33.1 | length 3.5
  Top Layer w0.254: R33.1@4.578,82.556 4.578,84.673 D5.2@5.561,85.656
NetD6_2: D6.2 R34.1 | length 3.1
  Top Layer w0.254: R34.1@3.258,82.556 D6.2@3.258,85.656
NetD7_1: D7.1 R20.2 | length 1.5
  Top Layer w0.152: D7.1@14.6,40.6 14.7,40.5 R20.2@14.7,39.1
NetF1_2: F1.2 F2.2 J14.2 TP8.1
  other v1: 49,85 51,85 53,85 55,85 57,85 59,85 61,85 63,85 65,85 67,85 69,85 71,85 73,85 75,85 77,85 50,86 52,86 54,86 56,86 58,86 60,86 62,86 64,86 66,86 68,86 70,86 72,86 74,86 76,86 78,86 49,87 51,87 53,87 55,87 57,87 59,87 61,87 63,87 65,87 67,87 69,87 71,87 73,87 75,87 77,87 50,88 56,88 62,88 64,88 66,88 68,88 70,88 72,88 74,88 76,88 78,88 49,89 51,89 55,89 61,89 63,89 67,89 69,89 71,89 73,89 77,89 50,90 56,90 62,90 68,90 70,90 72,90 78,90 78,90 49,91 51,91 53,91 55,91 57,91 59,91 61,91 63,91 67,91 69,91 71,91 73,91 77,91 77,91 50,92 52,92 54,92 56,92 58,92 60,92 62,92 64,92 66,92 68,92 70,92 72,92 74,92 76,92 78,92 49,93 51,93 53,93 55,93 57,93 59,93 61,93 63,93 65,93 67,93 69,93 71,93 73,93 75,93 77,93
NetJ1_2: J1.2 S1.1 | length 4.2
  Top Layer w0.152: J1.2@5.5,55.5 5.5,54.5 6.7,53.3 S1.1@6.7,51.8
NetJ2_1: J2.1 R5.2 | length 2.7
  Top Layer w0.152: J2.1@35.722,30.326 35.722,32.922 R5.2@35.8,33
NetJ2_3: J2.3 R6.2 | length 2.8
  Top Layer w0.152: J2.3@33.182,30.326 33.182,32.982 R6.2@33.3,33.1
NetJ2_5: J2.5 R7.2 | length 2.8
  Top Layer w0.152: J2.5@30.642,30.326 30.642,33.042 R7.2@30.7,33.1
NetJ2_7: J2.7 R8.2 | length 2.8
  Top Layer w0.152: R8.2@28.1,33.1 28.102,33.098 R8.2@28.102,33.082 J2.7@28.102,30.326
NetJ2_9: J2.9 R9.2 | length 2.8
  Top Layer w0.152: J2.9@25.562,30.326 25.562,32.962 R9.2@25.7,33.1
NetJ2_11: J2.11 R10.2 | length 2.8
  Top Layer w0.152: J2.11@23.022,30.326 23.022,33.022 R10.2@23.1,33.1
NetJ2_13: J2.13 R11.2 | length 2.7
  Top Layer w0.152: J2.13@20.4,30.4 20.5,30.5 R11.2@20.5,33.1
NetJ2_15: J2.15 R12.2 | length 2.8
  Top Layer w0.152: J2.15@17.942,30.326 17.942,33.042 R12.2@18,33.1
NetJ5_2: J5.2 R42.2 | length 2.7
  Top Layer w0.254: R42.2@20.062,95.208 20.062,96.784 20.676,97.398 J5.2@20.676,97.66
NetJ5_4: J5.4 R41.2 | length 2.8
  Top Layer w0.254: J5.4@18.136,97.66 19.011,96.784 R41.2@19.011,95.208
NetJ6_1: J6.1 L2.1 | length 3.3
  Top Layer w0.381: L2.1@26.174,96.81 27.54,96.81 27.991,97.261 J6.1@27.991,98.544
NetJ6_5: J6.5 L3.1 | length 1.9
  Top Layer w0.381: J6.5@30.591,98.544 30.591,97.43 L3.1@31.154,96.866
NetJ7_5: J7.5 R49.2 | length 3.1
  Top Layer w0.254: J7.5@15.555,65.248 15.555,68.336 R49.2@15.578,68.359
NetJ7_7: J7.7 R50.2 | length 3.1
  Top Layer w0.254: J7.7@13.015,65.248 13.015,68.341 R50.2@13.031,68.358
NetJ10_1: J10.1 R13.1 | length 2.8
  Top Layer w0.152: R13.1@13,33.1 13.07,33.03 J10.1@13.07,30.326
NetJ10_3: J10.3 R53.2 | length 2.9
  Top Layer w0.152: R53.2@10.5,33.2 10.53,33.17 J10.3@10.53,30.326
NetJ10_5: J10.5 R57.2 | length 2.8
  Top Layer w0.152: J10.5@7.99,30.326 7.99,33.09 R57.2@8,33.1
NetJ10_7: J10.7 R61.2 | length 2.8
  Top Layer w0.152: R61.2@5.4,33.1 5.45,33.05 J10.7@5.45,30.326
NetJ10_9: J10.9 R64.2 | length 2.8
  Top Layer w0.152: J10.9@2.91,30.326 2.91,33.01 R64.2@3,33.1
NetJ11_1: J11.1 R15.1 | length 3.2
  Top Layer w0.152: J11.1@37.284,11.94 37.284,14.984 R15.1@37.4,15.1
NetJ11_3: J11.3 R54.2 | length 3.3
  Top Layer w0.254: J11.3@34.744,12.031 R54.2@34.744,15.3
NetJ11_5: J11.5 R58.2 | length 3.3
  Top Layer w0.254: J11.5@32.204,12.031 32.204,15.239 R58.2@32.265,15.3
NetJ11_7: J11.7 R62.2 | length 3.3
  Top Layer w0.254: J11.7@29.664,12.031 R62.2@29.664,15.3
NetJ11_9: J11.9 R65.2 | length 3.3
  Top Layer w0.254: J11.9@27.124,12.031 27.124,15.248 R65.2@27.176,15.3
NetJ12_1: J12.1 R17.1 | length 3.3
  Top Layer w0.254: J12.1@22.657,12.031 R17.1@22.657,15.3
NetJ12_3: J12.3 R55.2 | length 3.3
  Top Layer w0.254: J12.3@20.117,12.031 20.117,15.269 R55.2@20.147,15.3
NetJ12_5: J12.5 R59.2 | length 3.3
  Top Layer w0.254: J12.5@17.577,12.031 R59.2@17.577,15.3
NetJ12_7: J12.7 R63.2 | length 3.3
  Top Layer w0.254: J12.7@15.037,12.031 R63.2@15.037,15.3
NetJ12_9: J12.9 R66.2 | length 3
  Top Layer w0.152: J12.9@12.497,11.94 12.497,14.897 R66.2@12.5,14.9
NetJ13_1: J13.1 R40.1 | length 2.8
  Top Layer w0.254: J13.1@7.95,12.456 R40.1@7.95,15.215
NetJ13_3: J13.3 R56.2 | length 2.8
  Top Layer w0.254: J13.3@5.41,12.456 5.41,15.124 R56.2@5.501,15.215
NetJ13_5: J13.5 R60.1 | length 2.9
  Top Layer w0.152: R60.1@2.8,15 2.86,14.94 J13.5@2.86,12.1
NetQ1_4: Q1.4 U4.2 U4.6 | length 16.8
  Top Layer w0.254: U4.6@43.475,79.075 43.475,80.075 44.8,81.4 ; U4.2@44.125,83.525 44.125,82.075 44.8,81.4 ; Q1.4@51.19,75.9 48.4,75.9 48,76.3 48,81.2 47.8,81.4 44.8,81.4
nFAULT: J4.5 R1.1 R3.1 R29.2 U1.26 | length 66
  Top Layer w0.152: R29.2@30.225,56.58 J4.5@33.22,56.58 ; v1(36.5,55.6) 36.6,55.6 R3.1@37.2,55 ; R3.1@37.205,54.995 39,56.79 R1.1@39,56.9 ; U1.26@62.8,24.925 62.825,24.9 63.7,24.9 64.905,26.105 64.905,43.054 66,44.149 v1(66,45.1)
  Bottom Layer w0.152: J4.5@33.4,56.5 34.3,55.6 v1(36.5,55.6) 44.4,47.7 55.1,47.7 57.7,45.1 v1(66,45.1)
nFAULT_MCU: R29.1 U3.16 | length 23.5
  Top Layer w0.152: U3.16@11.525,45.95 11.525,48.025 13,49.5 21.144,49.5 26.3,54.656 26.3,55.8 27.2,56.7 R29.1@28.7,56.7
nSCS/DIAG: J4.9 R16.1 R25.2 U1.2 | length 47
  Top Layer w0.152: R25.2@30.225,46.42 J4.9@33.38,46.42 ; R16.1@38.166,44.134 38.734,44.134 v1(39,44.4) ; v1(52.8,45) 54.044,45 55.357,43.687 55.357,26.144 55.902,25.6 56.975,25.6 U1.2@57,25.575
  Bottom Layer w0.152: J4.9@33.5,46.36 35.94,46.36 37.9,44.4 v1(39,44.4) 39.026,44.374 50.874,44.374 51.5,45 v1(52.8,45)
nSCS_MCU: R25.1 R68.2 U3.10 | length 21
  Top Layer w0.152: U3.10@13.475,52 13.475,53.875 R68.2@13.6,54 ; v1(13.5,50.3) U3.10@13.5,52 ; v1(22,46.4) 28.7,46.4 R25.1@28.8,46.5
  Bottom Layer w0.152: v1(13.5,50.3) 13.5,49.856 16.656,46.7 21.7,46.7 v1(22,46.4)
nSLEEP: J4.3 R31.2 U1.24 | length 71.9
  Top Layer w0.152: R31.2@30.225,61.66 J4.3@33.34,61.66 ; U1.24@62.8,23.625 62.875,23.7 63.7,23.7 65.711,25.711 65.711,42.411 66.7,43.4 v1(69.3,43.4)
  Bottom Layer w0.152: J4.3@33.4,61.7 35.6,61.7 38.5,58.8 47.6,49.7 64.5,49.7 69.3,44.9 v1(69.3,43.4)
nSLEEP_MCU: R31.1 U3.17 | length 28.4
  Top Layer w0.152: U3.17@12.175,45.95 12.175,47.975 13.348,49.148 21.448,49.148 27,54.7 v1(27,54.9) ; v1(27,61.6) 28.7,61.6 R31.1@28.8,61.7
  Bottom Layer w0.152: v1(27,54.9) v1(27,61.6)
OUT1: C3.1 C38.2 J3.1 TP2.1 U1.9 U1.10 U1.11
  other v1: 42,3 44,3 46,3 48,3 50,3 52,3 54,3 41,4 43,4 45,4 47,4 49,4 51,4 53,4 55,4 42,5 44,5 46,5 48,5 50,5 52,5 54,5 41,6 43,6 45,6 47,6 49,6 51,6 53,6 55,6 42,7 46,7 50,7 52,7 54,7 41,8 45,8 51,8 53,8 55,8 42,9 46,9 50,9 52,9 54,9 41,10 43,10 45,10 47,10 49,10 51,10 53,10 55,10 42,11 44,11 46,11 48,11 50,11 52,11 54,11 41,12 45,12 47,12 51,12 53,12 55,12 46,13 50,13 52,13 54,13 41,14 45,14 47,14 51,14 53,14 55,14 42,15 44,15 46,15 48,15 50,15 52,15 54,15 41,16 43,16 45,16 47,16 49,16 51,16 53,16 42,17 44,17 46,17 48,17 50,17 52,17 54,17 41,18 43,18 45,18 47,18 51,18 53,18 55,18 42,19 44,19 46,19 52,19 54,19 41,20 43,20 45,20 47,20 51,20 53,20 55,20
OUT2: C3.2 C39.2 J8.1 TP5.1 U1.18 U1.19 U1.20
  other v1: 66,3 68,3 70,3 72,3 74,3 76,3 78,3 65,4 67,4 69,4 71,4 73,4 75,4 77,4 79,4 66,5 68,5 70,5 72,5 74,5 76,5 78,5 65,6 67,6 69,6 71,6 73,6 75,6 77,6 79,6 66,7 68,7 70,7 74,7 78,7 65,8 67,8 69,8 75,8 79,8 66,9 68,9 70,9 74,9 78,9 65,10 67,10 69,10 71,10 73,10 75,10 77,10 79,10 66,11 68,11 70,11 72,11 74,11 76,11 78,11 65,12 67,12 69,12 73,12 75,12 79,12 66,13 68,13 70,13 74,13 65,14 67,14 69,14 73,14 75,14 79,14 66,15 68,15 70,15 72,15 74,15 76,15 78,15 67,16 69,16 71,16 73,16 75,16 77,16 79,16 66,17 68,17 70,17 72,17 74,17 76,17 78,17 65,18 67,18 69,18 71,18 75,18 77,18 79,18 66,19 68,19 70,19 76,19 78,19 65,20 67,20 69,20 71,20 75,20 77,20 79,20
P1.4: TP3.1 U3.6 | length 10.7
  Top Layer w0.152: TP3.1@10.7,55.5 10.7,56.5 11.1,56.9 14.6,56.9 15.824,55.676 15.824,54.011 16.075,53.759 U3.6@16.075,51.85
P_IN: C6.2 C7.2 C8.2 C9.1 C14.1 L1.1 Q1.5 Q1.6 Q1.7 Q1.8 Q1.9@53.3,72.395 U4.8
  other v1: 46,63 48,63 50,63 52,63 54,63 56,63 58,63 60,63 62,63 45,64 47,64 49,64 51,64 53,64 55,64 57,64 59,64 61,64 46,65 48,65 50,65 52,65 54,65 56,65 58,65 60,65 62,65 45,66 47,66 49,66 51,66 53,66 55,66 57,66 59,66 61,66 46,67 54,67 56,67 62,67 45,68 47,68 55,68 46,69 54,69 56,69 62,69 47,70 49,70 51,70 57,70 59,70 61,70 46,71 48,71 50,71 56,71 58,71 60,71 62,71 47,72 49,72 57,72 59,72 61,72 46,73 48,73 50,73 56,73 58,73 60,73 62,73 47,74 49,74 57,74 59,74 61,74 46,75 48,75 47,76 46,77 45,78
PH/IN2: J4.10 R24.2 U1.3 | length 45
  Top Layer w0.152: R24.2@30.225,43.88 J4.10@33.22,43.88 ; v1(53.9,44.4) 55.005,43.295 55.005,25.998 56.103,24.9 56.975,24.9 U1.3@57,24.925
  Bottom Layer w0.152: J4.10@33.5,43.82 33.532,43.852 39.197,43.852 39.349,44.005 51.505,44.005 51.926,44.426 53.874,44.426 v1(53.9,44.4)
PH/IN2_MCU: R24.1 U3.12 | length 21.2
  Top Layer w0.152: v1@12.175,49.625 U3.12@12.175,51.85 ; v1(22,43.9) 28.7,43.9 R24.1@28.8,43.8
  Bottom Layer w0.152: v1(12.2,49.6) 15.5,46.3 19.6,46.3 v1(22,43.9)
PUSH: J1.3 R18.1 U3.5 | length 14
  Top Layer w0.152: J1.3@8,55.6 9.9,57.5 14.9,57.5 16.7,55.7 16.7,54.6 U3.5@16.7,51.9
RST/SBWTDIO: J1.1 J7.4 U3.24 | length 42.6
  Top Layer w0.152: U3.24@16.725,45.95 16.725,47.225 v1(16.8,47.3)
  Bottom Layer w0.152: J1.1@2.96,55.6 2.96,62.66 4.3,64 16.8,64 20.526,60.274 20.526,55.282 19.921,54.677 19.921,50.421 v1(16.8,47.3)
SCLK/SR: J4.8 R26.2 R39.1 U1.1 | length 47
  Top Layer w0.152: R26.2@30.225,48.96 J4.8@33.24,48.96 ; R39.1@38.166,46.334 v1(38.7,45.8) ; v1(53.9,45.6) 53.943,45.6 55.71,43.833 55.71,26.433 55.917,26.225 U1.1@57,26.225
  Bottom Layer w0.152: J4.8@33.4,49 J4.8@33.5,48.9 35.6,48.9 v1(38.7,45.8) 53.7,45.8 v1(53.9,45.6)
SCLK_MCU: R26.1 U3.7 | length 14.8
  Top Layer w0.152: U3.7@15.425,51.85 15.425,50.846 16.171,50.1 v1(21,50.1) ; v1(27,48.9) R26.1@28.6,48.9
  Bottom Layer w0.152: v1(21,50.1) 22.1,49 v1@26.9,49
SDI/ITRIP: J4.7 R14.1 R27.2 U1.28 | length 56.8
  Top Layer w0.152: R27.2@30.225,51.5 J4.7@33.4,51.5 ; R14.1@38.166,48.734 v1(38.7,48.2) ; U1.28@62.8,26.225 63.8,26.225 64.2,26.625 v1(64.2,43.7)
  Bottom Layer w0.152: J4.7@33.2,51.6 33.3,51.5 35.4,51.5 v1(38.7,48.2) 39.974,46.926 54.318,46.926 57.544,43.7 v1(64.2,43.7)
SDI_MCU: R27.1 U3.23 | length 15.8
  Top Layer w0.152: U3.23@16.075,45.95 16.1,45.95 16.1,47.344 17.199,48.443 21.943,48.443 25,51.5 R27.1@28.8,51.5
SDO/MODE: J4.6 R28.2 R52.1 U1.27 | length 60
  Top Layer w0.152: R28.2@30.225,54.04 J4.6@33.26,54.04 ; R52.1@38.366,51.134 38.466,51.134 v1@39.05,50.55 ; U1.27@62.8,25.575 62.825,25.6 63.698,25.6 64.552,26.454 64.552,43.2 65.1,43.748 v1(65.1,44.4)
  Bottom Layer w0.152: J4.6@33.4,54 35.5,54 v1(39,50.5) v1@39,50.456 ; v1@39,50.6 42.321,47.279 54.821,47.279 57.7,44.4 v1(65.1,44.4)
SDO_MCU: R28.1 U3.22 | length 17.8
  Top Layer w0.152: U3.22@15.425,45.95 15.4,45.95 15.4,47.7 16.495,48.795 21.795,48.795 27.04,54.04 R28.1@28.775,54.04
STATUS: D1.2 TP6.1 U3.18 | length 6.9
  Top Layer w0.152: TP6.1@9.5,41.9 10.5,41.9 11.3,42.7 D1.2@12.9,42.7 ; D1.2@12.8,42.75 U3.18@12.8,45.9
T_RST_RST: R48.1 U5.43 | length 9.1
  Top Layer w0.254: R48.1@18.943,69.206 21.22,71.482 21.22,73.797 U5.43@19.011,76.005 19.313,75.703
T_TEST_TCKC: R47.1 U5.44 | length 8.3
  Top Layer w0.254: U5.44@19.365,76.359 21.835,73.889 21.835,69.574 R47.1@21.467,69.206
TST/SBWTCK: J7.2 U3.25 | length 19.1
  Top Layer w0.152: U3.25@17.375,45.95 17.375,46.954 18.321,47.9 v1(19,47.9)
  Bottom Layer w0.152: v1(19,47.9) 20.274,49.174 20.274,54.33 20.974,55.03 20.974,55.818 21.282,56.126 21.282,61.918 J7.2@20.5,62.7
USB_D_N: J6.2 R43.1 U7.2 U7.5 | length 8.4
  Top Layer w0.16: R43.1@28.559,90.808 28.903,91.152 U7.2@28.903,91.903 28.903,92.445 28.434,92.914 28.434,93.866 28.903,94.32 28.903,97.512 28.641,97.774 J6.2@28.641,98.544
USB_D_P: J6.3 R44.1 U7.3 | length 8.3
  Top Layer w0.16: J6.3@29.291,98.544 29.291,97.71 29.317,97.683 29.317,94.149 28.859,93.691 28.859,93.075 29.403,92.531 U7.3@29.403,91.903 29.403,91.133 R44.1@29.728,90.808
VBAT: C16.1 D4.2 F1.1 F2.1 Q1.1 Q1.2 Q1.3 U4.4 | length 8.8
  Top Layer w0.254: C16.1@42.816,85.4 43.416,84.8 45.3,84.8 46.3,83.8 49.1,83.8 ; U4.4@42.825,83.525 C16.1@42.825,85.375 ; F2.1@52.49,79.41 F2.1@52.5,79.4
  other v1: 57,76 59,76 61,76 50,77 52,77 54,77 56,77 58,77 60,77 62,77 49,78 51,78 55,78 61,78 50,79 56,79 62,79 49,80 51,80 55,80 61,80 50,81 56,81 62,81 49,82 51,82 53,82 55,82 57,82 59,82 61,82 50,83 52,83 54,83 56,83 58,83
VM: C1.1 C2.1 C4.1 C10.1 C11.1 C12.2 C13.2 C15.1 D3.2 J9.1 L1.2 TP1.1 U1.6 U1.7 U1.8 U1.21 U1.22 U1.23 U2.8
  other v1: 42,22 44,22 46,22 48,22 50,22 52,22 54,22 56,22 64,22 66,22 68,22 70,22 72,22 74,22 76,22 78,22 41,23 43,23 45,23 47,23 49,23 51,23 53,23 55,23 65,23 67,23 69,23 71,23 73,23 75,23 77,23 79,23 42,24 44,24 46,24 48,24 50,24 52,24 54,24 66,24 68,24 70,24 72,24 74,24 76,24 78,24 41,25 43,25 45,25 47,25 49,25 51,25 53,25 67,25 69,25 71,25 73,25 75,25 77,25 79,25 42,26 44,26 46,26 48,26 50,26 52,26 68,26 70,26 72,26 74,26 76,26 78,26 41,27 43,27 45,27 47,27 49,27 51,27 53,27 67,27 69,27 71,27 73,27 75,27 77,27 79,27 42,28 44,28 46,28 48,28 50,28 52,28 68,28 70,28 72,28 74,28 76,28 78,28 41,29 43,29 45,29 47,29 49,29 51,29 53,29 67,29 69,29 71,29 73,29 75,29 77,29 79,29 42,30 44,30 46,30 48,30 50,30 52,30 68,30 70,30 72,30 74,30 76,30 78,30 41,31 43,31 45,31 47,31 49,31 51,31 53,31 67,31 71,31 73,31 77,31 79,31 42,32 44,32 46,32 50,32 52,32 68,32 72,32 76,32 78,32 41,33 43,33 45,33 47,33 49,33 51,33 53,33 67,33 71,33 73,33 77,33 79,33 42,34 44,34 46,34 48,34 50,34 52,34 68,34 70,34 72,34 74,34 76,34 78,34 41,35 43,35 45,35 47,35 49,35 51,35 53,35 67,35 69,35 71,35 73,35 75,35 77,35 79,35 42,36 44,36 46,36 48,36 50,36 52,36 58,36 60,36 62,36 68,36 72,36 76,36 78,36 41,37 43,37 45,37 47,37 49,37 51,37 53,37 57,37 59,37 61,37 63,37 67,37 71,37 73,37 77,37 79,37 42,38 44,38 46,38 48,38 50,38 52,38 58,38 62,38 68,38 72,38 76,38 78,38 41,39 43,39 45,39 47,39 49,39 51,39 53,39 57,39 59,39 61,39 63,39 67,39 69,39 71,39 73,39 75,39 77,39 79,39 42,40 44,40 46,40 48,40 50,40 52,40 58,40 62,40 68,40 70,40 72,40 74,40 76,40 78,40 41,41 43,41 45,41 47,41 49,41 51,41 53,41 57,41 59,41 61,41 63,41 67,41 69,41 71,41 73,41 75,41 77,41 79,41 46,53 48,53 50,53 52,53 54,53 56,53 58,53 60,53 62,53 47,54 49,54 51,54 53,54 55,54 57,54 59,54 61,54 46,55 48,55 50,55 52,55 54,55 56,55 58,55 60,55 62,55 45,56 47,56 49,56 51,56 53,56 55,56 63,56 46,57 54,57 56,57 62,57 45,58 47,58 53,58 55,58 57,58 59,58 61,58 63,58 46,59 54,59 56,59 58,59 60,59 62,59
pads on no net: FID1.1 FID2.1 FID3.1 H1.0 H2.0 H3.0 H4.0 J5.6 J5.10 J5.12 J5.13 J5.14 J6.4 J7.11 J7.12 LBL1.0 Q1.9@51.85,72 Q1.9@51.85,73.78 Q1.9@53.3,72 Q1.9@53.3,72.85 Q1.9@53.3,73.78 Q1.9@54.75,72 Q1.9@54.75,73.78 S1.2 U3.11 U3.14 U3.15 U3.19 U3.20 U3.21 U4.3 U4.5 U5.3 U5.4 U5.5 U5.6 U5.7 U5.8 U5.10 U5.12 U5.13 U5.18 U5.19 U5.22 U5.23 U5.24 U5.25 U5.26 U5.27 U5.28 U5.29 U5.30 U5.31 U5.32 U5.33 U5.34 U5.35 U5.36 U5.41 U5.42 U5.45 U5.46 U5.47 U5.48 U6.7@23.751,89.734 U6.7@24.651,89.734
